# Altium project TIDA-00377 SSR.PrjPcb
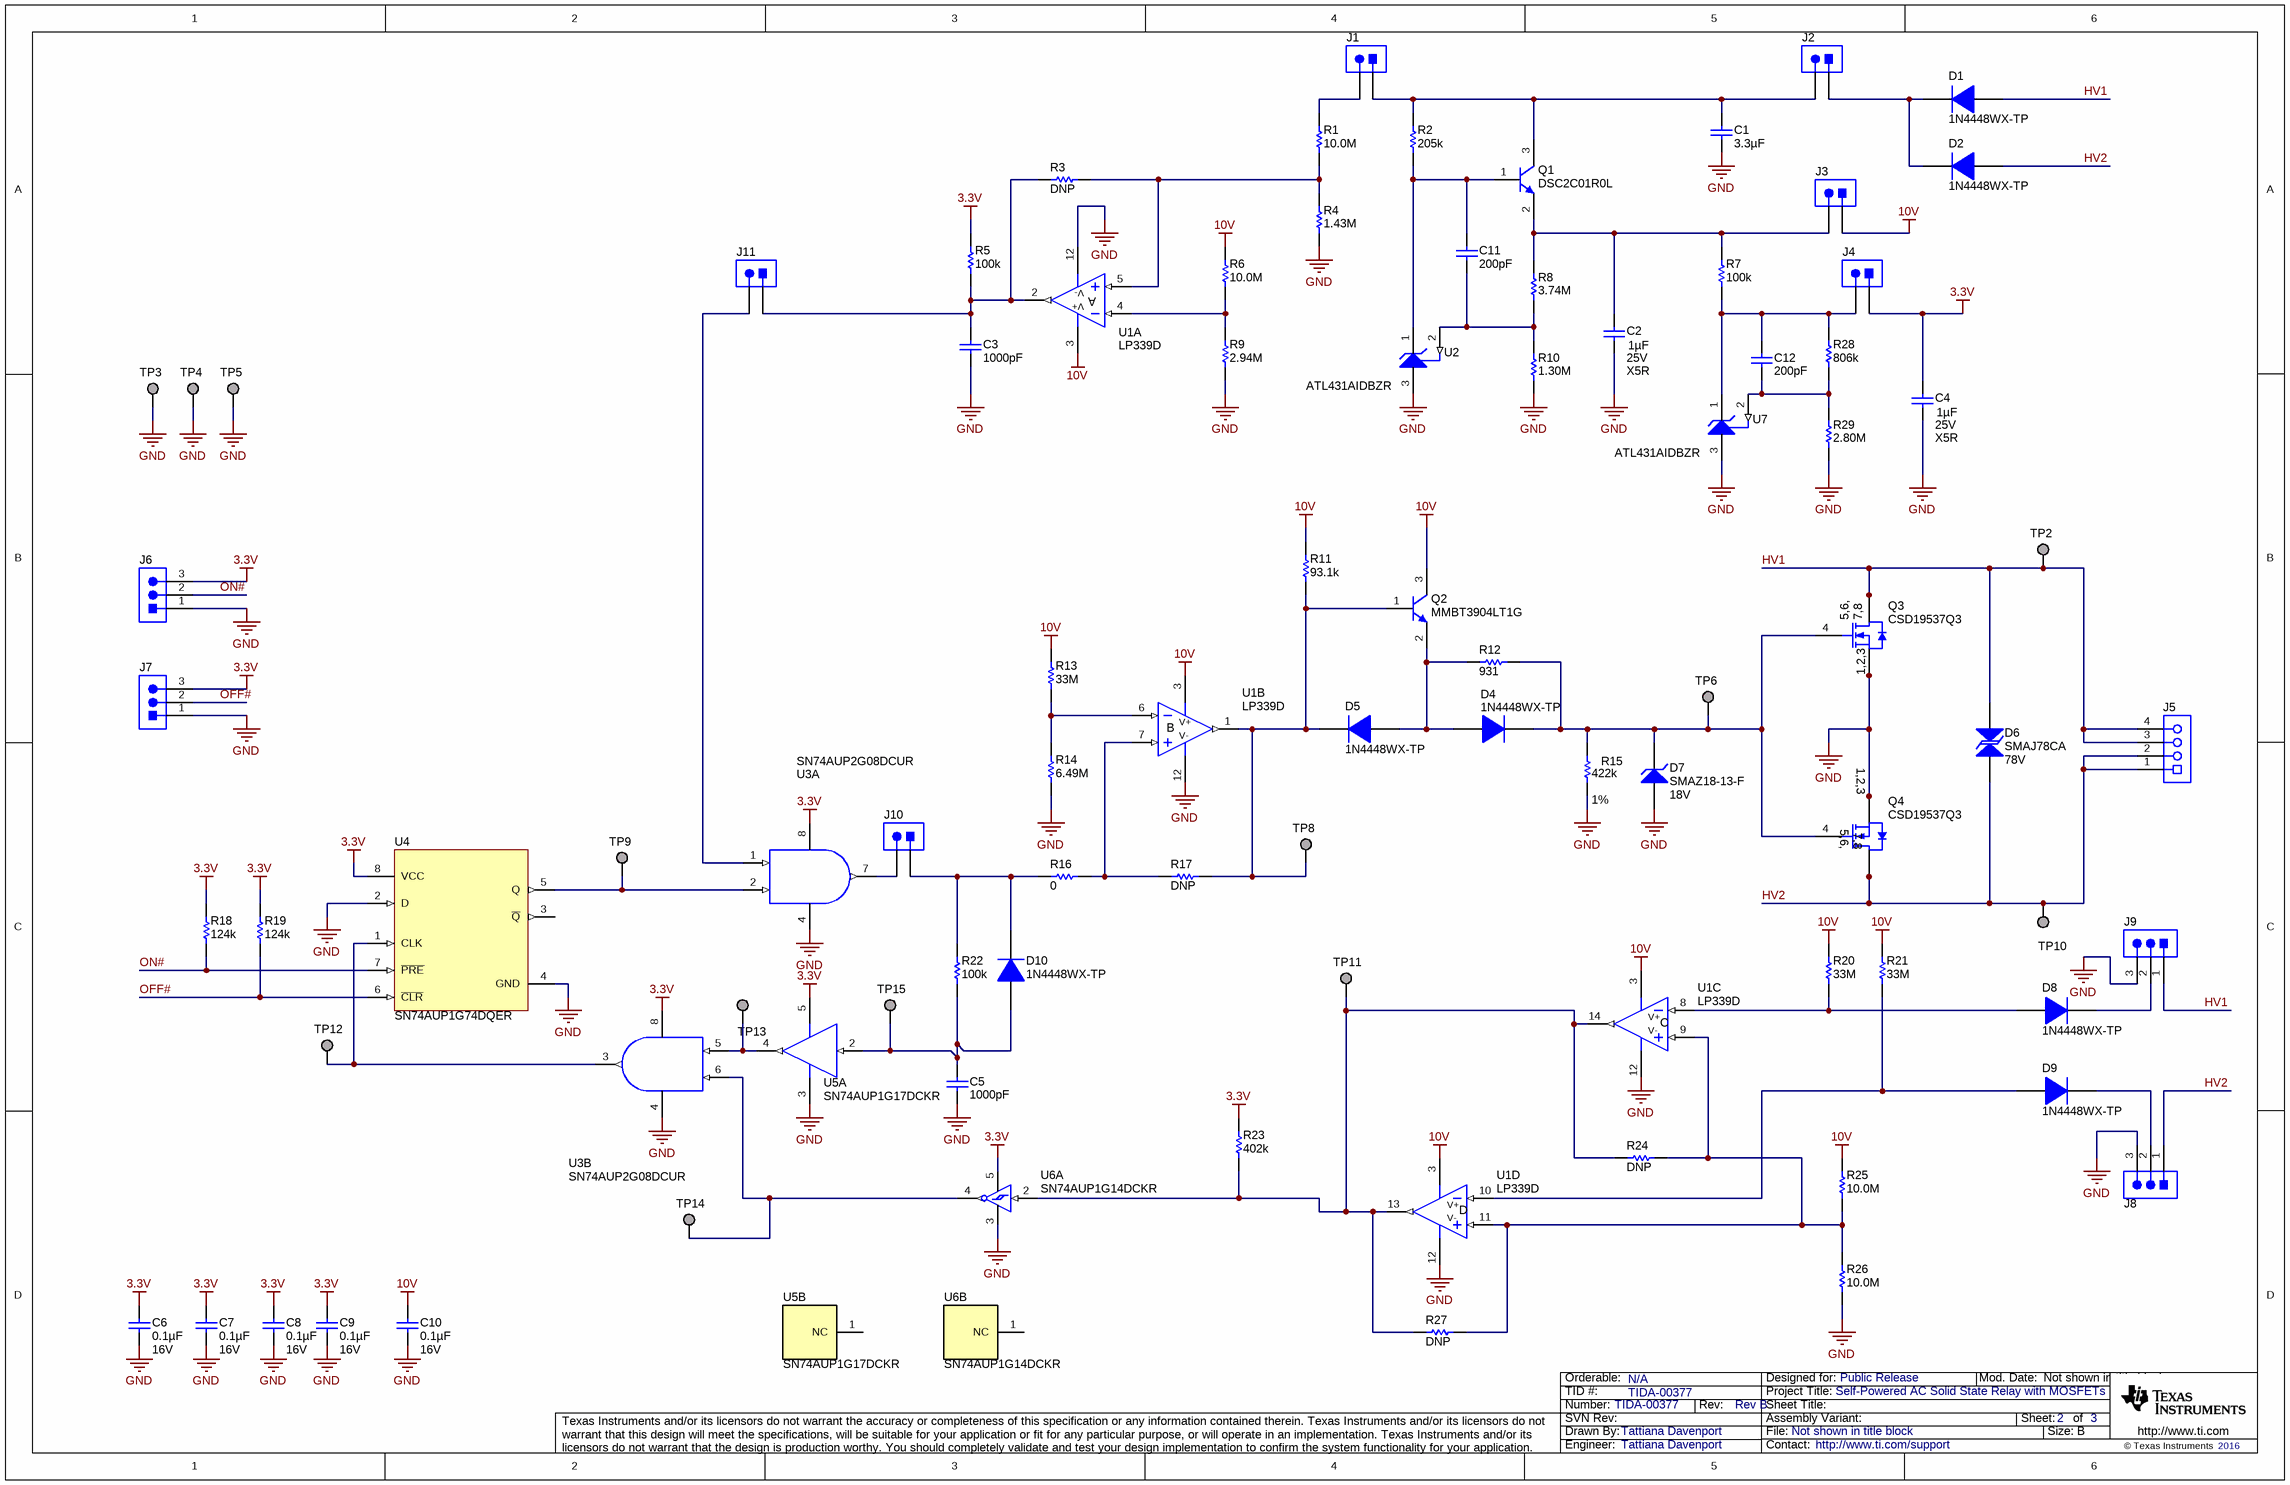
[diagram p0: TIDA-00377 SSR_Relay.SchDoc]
CopyrightYear: 2016; EVM_Orderable: N/A; PCB_Rev: Rev B; PRJ_Customer: Public Release; PRJ_Engineer: Tattiana Davenport; PRJ_Number: TIDA-00377; PRJ_Title: Self-Powered AC Solid State Relay with MOSFETs; SCH_Rev: Rev B; TechSupport: http://www.ti.com/support; TID: TIDA-00377
3 sheets, 114 parts. Net scope: global (net labels, ports and power ports of the same name join across sheets).
Board file: TIDA-00377 SSR_TID.PcbDoc
Sheets:
  TIDA-00377 SSR_Relay.SchDoc
  TIDA-00377 SSR_CoverSheet.SchDoc
  TIDA-00377 SSR_TID_Hardware.SchDoc

## Sheet TIDA-00377 SSR_Relay.SchDoc
size 431 x 279 mm; Date: Not shown in title block; ApprovedBy: Not shown in title block; CheckedBy: Not shown in title block; Author: Not shown in title block; CompanyName: Not shown in title block; DrawnBy: Tattiana Davenport; Engineer: Not shown in title block; Organization: Not shown in title block; Address1: Not shown in title block; Address2: Not shown in title block; Address3: Not shown in title block; Address4: Not shown in title block; DocumentNumber: 1; Revision: Use project parameter SCH_Rev; SheetNumber: 2; SheetTotal: 3; PageSetup: Record=PageOptions¦CenterHorizontal=True¦CenterVertical=True¦PrintScale=1.00¦XCorrection=1.00¦YCorrection=1.00¦PrintKind=0¦BorderSize=5000000¦LeftOffset=0¦BottomOffset=0¦Orientation=2¦PaperLength=1000¦PaperWidth=1000¦Scale=100¦PaperSource=15¦PrintQuality=-3¦MediaType=1¦DitherType=10¦PrintScaleMode=1¦PaperKind=Letter¦PaperIndex=1

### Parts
C1  ValueDisplayed: 3.3µF  [1210]  (hidden comment: C3225X7S2A335M200AB)
C2  ValueDisplayed: 1µF  Value2: 25V  TempCo: X5R  [0603]  (hidden comment: GRM188R61E105KA12D)
C3  ValueDisplayed: 1000pF  [0603]  (hidden comment: GRM188R71E102KA01D)
C4  ValueDisplayed: 1µF  Value2: 25V  TempCo: X5R  [0603]  (hidden comment: GRM188R61E105KA12D)
C5  ValueDisplayed: 1000pF  [0603]  (hidden comment: GRM188R71E102KA01D)
C6  ValueDisplayed: 0.1µF  Value2: 16V  [0603]  (hidden comment: GRM188R71C104KA01D)
C7  ValueDisplayed: 0.1µF  Value2: 16V  [0603]  (hidden comment: GRM188R71C104KA01D)
C8  ValueDisplayed: 0.1µF  Value2: 16V  [0603]  (hidden comment: GRM188R71C104KA01D)
C9  ValueDisplayed: 0.1µF  Value2: 16V  [0603]  (hidden comment: GRM188R71C104KA01D)
C10  ValueDisplayed: 0.1µF  Value2: 16V  [0603]  (hidden comment: GRM188R71C104KA01D)
C11  ValueDisplayed: 200pF  [0603]  (hidden comment: GRM1885C1H201JA01D)
C12  ValueDisplayed: 200pF  [0603]  (hidden comment: GRM1885C1H201JA01D)
D1  1N4448WX-TP  [sod-323]
D2  1N4448WX-TP  [sod-323]
D4  1N4448WX-TP  [sod-323]
D5  1N4448WX-TP  [sod-323]
D6  SMAJ78CA  value 78V  [SMA]
D7  SMAZ18-13-F  value 18V  [SMA]
D8  1N4448WX-TP  [sod-323]
D9  1N4448WX-TP  [sod-323]
D10  1N4448WX-TP  [sod-323]
J1  5-146278-2  [TE_5-146278-2]  (value not drawn)
J2  5-146278-2  [TE_5-146278-2]  (value not drawn)
J3  5-146278-2  [TE_5-146278-2]  (value not drawn)
J4  5-146278-2  [TE_5-146278-2]  (value not drawn)
J5  282834-4  [TEC_282834-4]  (value not drawn)
J6  5-146278-3  [TE_5-146278-3]  (value not drawn)
J7  5-146278-3  [TE_5-146278-3]  (value not drawn)
J8  5-146278-3  [TE_5-146278-3]  (value not drawn)
J9  5-146278-3  [TE_5-146278-3]  (value not drawn)
J10  5-146278-2  [TE_5-146278-2]  (value not drawn)
J11  5-146278-2  [TE_5-146278-2]  (value not drawn)
Q1  DSC2C01R0L  [SOT-23]
Q2  MMBT3904LT1G  [SOT-23]
Q3  CSD19537Q3  [DQG0008A]
Q4  CSD19537Q3  [DQG0008A]
R1  ValueDisplayed: 10.0M  [0805_HV]  (hidden comment: CRCW080510M0FKEA)
R2  ValueDisplayed: 205k  [0805_HV]  (hidden comment: CRCW0805205KFKEA)
R3  ValueDisplayed: DNP  [0805_HV]  (hidden comment: CRCW08050000Z0EA)
R4  ValueDisplayed: 1.43M  [0805_HV]  (hidden comment: CRCW08051M43FKEA)
R5  ValueDisplayed: 100k  [0805_HV]  (hidden comment: CRCW0805100KFKEA)
R6  ValueDisplayed: 10.0M  [0805_HV]  (hidden comment: CRCW080510M0FKEA)
R7  ValueDisplayed: 100k  [0805_HV]  (hidden comment: CRCW0805100KFKEA)
R8  ValueDisplayed: 3.74M  [0805_HV]  (hidden comment: CRCW08053M74FKEA)
R9  ValueDisplayed: 2.94M  [0805_HV]  (hidden comment: CRCW08052M94FKEA)
R10  ValueDisplayed: 1.30M  [0805_HV]  (hidden comment: CRCW08051M30FKEA)
R11  ValueDisplayed: 93.1k  [0805_HV]  (hidden comment: CRCW080593K1FKEA)
R12  ValueDisplayed: 931  [0805_HV]  (hidden comment: CRCW0805931RFKEA)
R13  ValueDisplayed: 33M  [0805_HV]  (hidden comment: RC0805JR-0733ML)
R14  ValueDisplayed: 6.49M  [0805_HV]  (hidden comment: CRCW08056M49FKEA)
R15  ValueDisplayed: 422k  Value1: 1%  [0805_HV]  (hidden comment: CRCW0805422KFKEA)
R16  ValueDisplayed: 0  [0805_HV]  (hidden comment: CRCW08050000Z0EA)
R17  ValueDisplayed: DNP  [0805_HV]  (hidden comment: CRCW08050000Z0EA)
R18  ValueDisplayed: 124k  [0402]  (hidden comment: CRCW0402124KFKED)
R19  ValueDisplayed: 124k  [0402]  (hidden comment: CRCW0402124KFKED)
R20  ValueDisplayed: 33M  [0805_HV]  (hidden comment: RC0805JR-0733ML)
R21  ValueDisplayed: 33M  [0805_HV]  (hidden comment: RC0805JR-0733ML)
R22  ValueDisplayed: 100k  [0805_HV]  (hidden comment: CRCW0805100KFKEA)
R23  ValueDisplayed: 402k  [0805_HV]  (hidden comment: CRCW0805402KFKEA)
R24  ValueDisplayed: DNP  [0805_HV]  (hidden comment: CRCW08050000Z0EA)
R25  ValueDisplayed: 10.0M  [0805_HV]  (hidden comment: CRCW080510M0FKEA)
R26  ValueDisplayed: 10.0M  [0805_HV]  (hidden comment: CRCW080510M0FKEA)
R27  ValueDisplayed: DNP  [0805_HV]  (hidden comment: CRCW08050000Z0EA)
R28  ValueDisplayed: 806k  [0805_HV]  (hidden comment: CRCW0805806KFKEA)
R29  ValueDisplayed: 2.80M  [0805_HV]  (hidden comment: CRCW08052M80FKEA)
TP2  TESTPOINT  [Keystone_5019]  (value not drawn)  (no BOM)
TP3  TESTPOINT  [Keystone_5019]  (value not drawn)  (no BOM)
TP4  TESTPOINT  [Keystone_5019]  (value not drawn)  (no BOM)
TP5  TESTPOINT  [Keystone_5019]  (value not drawn)  (no BOM)
TP6  TESTPOINT  [Keystone_5019]  (value not drawn)  (no BOM)
TP8  TESTPOINT  [Keystone_5019]  (value not drawn)  (no BOM)
TP9  TESTPOINT  [Keystone_5019]  (value not drawn)  (no BOM)
TP10  TESTPOINT  [Keystone_5019]  (value not drawn)  (no BOM)
TP11  TESTPOINT  [Keystone_5019]  (value not drawn)  (no BOM)
TP12  TESTPOINT  [Keystone_5019]  (value not drawn)  (no BOM)
TP13  TESTPOINT  [Keystone_5019]  (value not drawn)  (no BOM)
TP14  TESTPOINT  [Keystone_5019]  (value not drawn)  (no BOM)
TP15  TESTPOINT  [Keystone_5019]  (value not drawn)  (no BOM)
U1  LP339D  [D0014A_N]  (parts A,B,C,D of 4)
U2  ATL431AIDBZR  [DBZ0003A_M]
U3  SN74AUP2G08DCUR  [DCU0008A_N]  (parts A,B of 2)
U4  SN74AUP1G74DQER  [DQE0008A]
U5  SN74AUP1G17DCKR  [DCK0005A_N]  (parts A,B of 2)
U6  SN74AUP1G14DCKR  [DCK0005A_N]  (parts A,B of 2)
U7  ATL431AIDBZR  [DBZ0003A_M]

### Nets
3.3V: C4.2 C6.2 C7.2 C8.2 C9.2 J4.1 J6.3 J7.3 R5.1 R18.2 R19.2 R23.1 U3.8(V+) U4.8(VCC) U5.5(VCC) U6.5(VCC)
10V: C10.2 J3.1 Q2.3(C) R6.1 R11.1 R13.1 R20.1 R21.1 R25.1 U1.3(V+)
GND: C1.1 C2.1 C3.1 C4.1 C5.1 C6.1 C7.1 C8.1 C9.1 C10.1 D7.2(A) J6.1 J7.1 J8.3 J9.3 Q3.1(S) Q3.2(S) Q3.3(S) Q4.1(S) Q4.2(S) Q4.3(S) R4.2 R9.2 R10.2 R14.2 R15.1 R26.2 R29.2 TP3.1 TP4.1 TP5.1 U1.12(V-) U2.3(ANODE) U3.4(V-) U4.2(D) U4.4(GND) U5.3(GND) U6.3(GND) U7.3(ANODE)
HV1: D1.2(A) D6.2 J5.3 J5.4 J9.1 Q3.5(D) Q3.6(D) Q3.7(D) Q3.8(D) Q3.9(D) TP2.1
HV2: D2.2(A) D6.1 J5.1 J5.2 J8.1 Q4.5(D) Q4.6(D) Q4.7(D) Q4.8(D) Q4.9(D) TP10.1
OFF#: J7.2 R19.1 U4.6(~{CLR})
ON#: J6.2 R18.1 U4.7(~{PRE})
NetC1_2: C1.2 J1.1 J2.2 Q1.3(C) R2.1
NetC2_2: C2.2 J3.2 Q1.2(E) R7.1 R8.1
NetC3_2: C3.2 J11.1 R3.1 R5.2 U1.2(OUT1)
NetC5_2: C5.2 D10.2(A) R22.2 TP15.1 U5.2(A)
NetC11_1: C11.1 R8.2 R10.1 U2.2(REF)
NetC11_2: C11.2 Q1.1(B) R2.2 U2.1(CATHODE)
NetC12_1: C12.1 R28.2 R29.1 U7.2(REF)
NetC12_2: C12.2 J4.2 R7.2 R28.1 U7.1(CATHODE)
NetD1_1: D1.1(K) D2.1(K) J2.1
NetD4_1: D4.1(K) D7.1(K) Q3.4(G) Q4.4(G) R12.2 R15.2 TP6.1
NetD4_2: D4.2(A) D5.2(A) Q2.2(E) R12.1
NetD5_1: D5.1(K) Q2.1(B) R11.2 R17.2 TP8.1 U1.1(OUT2)
NetD8_1: D8.1(K) J9.2
NetD8_2: D8.2(A) R20.2 U1.8(-IN3)
NetD9_1: D9.1(K) J8.2
NetD9_2: D9.2(A) R21.2 U1.10(-IN4)
NetD10_1: D10.1(K) J10.1 R16.1 R22.1
NetJ1_2: J1.2 R1.1
NetJ10_2: J10.2 U3.7(1Y)
NetJ11_2: J11.2 U3.1(1A)
NetR1_2: R1.2 R3.2 R4.1 U1.5(+IN1)
NetR6_2: R6.2 R9.1 U1.4(-IN1)
NetR13_2: R13.2 R14.1 U1.6(-IN2)
NetR16_2: R16.2 R17.1 U1.7(+IN2)
NetR23_2: R23.2 R24.1 R27.1 TP11.1 U1.13(OUT4) U1.14(OUT3) U6.2(A)
NetR24_2: R24.2 R25.2 R26.1 R27.2 U1.9(+IN3) U1.11(+IN4)
NetTP9_1: TP9.1 U3.2(1B) U4.5(Q)
NetTP12_1: TP12.1 U3.3(2Y) U4.1(CLK)
NetTP13_1: TP13.1 U3.5(2A) U5.4(Y)
NetTP14_1: TP14.1 U3.6(2B) U6.4(Y)

Not connected (* = marked no-connect by the designer): U4 3(~{Q}); U5 1(NC); U6 1(NC)

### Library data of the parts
C1 = C3225X7S2A335M200AB: CAP, CERM, 3.3 µF, 100 V, +/- 20%, X7S, 1210; Manufacturer: TDK; Polarized: N; CompType: Capacitor; Value: 3.3uF; U/M: EA; Cap_F: 0.0000033; Tolerance_%: 20; Value1: Unknown; VDC_V: 100; Value2: 100V; TaMin_C: -55; TaMax_C: 125; AEC Category: Q200
C2 C4 = GRM188R61E105KA12D: CAP, CERM, 1 µF, 25 V, +/- 10%, X5R, 0603; Manufacturer: MuRata; Polarized: N; CompType: Capacitor; Value: 1uF; U/M: EA; Cap_F: 0.000001; Tolerance_%: 10; Value1: Unknown; VDC_V: 25; TaMin_C: -55; TaMax_C: 85; AEC Category: Q200
C3 C5 = GRM188R71E102KA01D: CAP, CERM, 1000 pF, 25 V, +/- 10%, X7R, 0603; Manufacturer: MuRata; Polarized: N; CompType: Capacitor; Value: 1000pF; U/M: EA; Cap_F: 0.000000001; Tolerance_%: 10; Value1: Unknown; VDC_V: 25; Value2: 25V; TaMin_C: -55; TaMax_C: 125; AEC Category: Q200
C6-C10 = GRM188R71C104KA01D: CAP, CERM, 0.1 µF, 16 V, +/- 10%, X7R, 0603; Manufacturer: MuRata; Polarized: N; CompType: Capacitor; Value: 0.1uF; U/M: EA; Cap_F: 0.0000001; Tolerance_%: 10; Value1: Unknown; VDC_V: 16; TaMin_C: -55; TaMax_C: 125; AEC Category: Q200
C11 C12 = GRM1885C1H201JA01D: CAP, CERM, 200 pF, 50 V, +/- 5%, C0G/NP0, 0603; Manufacturer: MuRata; Polarized: N; CompType: Capacitor; Value: 200pF; U/M: EA; Cap_F: 0.0000000002; Tolerance_%: 5; Value1: Unknown; VDC_V: 50; Value2: 50V; TaMin_C: -55; TaMax_C: 125; AEC Category: Q200
D1 D2 D4 D5 D8-D10 = 1N4448WX-TP: Diode, Switching, 75 V, 0.25 A, SOD-323; Manufacturer: Micro Commercial Components; U/M: EA; Value: 75V; Value1: 0.25A; Io_A: 0.25; Vr_V: 75; TJmax_C: 150; AEC Category: Q101
D6 = SMAJ78CA: Diode, TVS, Bi, 78 V, 400 W, SMA; Manufacturer: Littelfuse; U/M: EA; Power_W: 400; Vr_V: 78; Value1: 400W; RJA_CperW: 120; AEC Category: Q101
D7 = SMAZ18-13-F: Diode, Zener, 18 V, 1 W, AEC-Q101, SMA; Manufacturer: Diodes Inc.; SymbolCreator: a0412235; U/M: EA; Power_W: 1; Vz_V: 18; Value1: 1W; RJA_CperW: 125; AEC Category: Q101; AEC Qualified: Y
J1-J4 J10 J11 = 5-146278-2: Header, 100mil, 2x1, Tin, TH; Manufacturer: TE Connectivity; SymbolCreator: a0412235; U/M: EA
J5 = 282834-4: Terminal Block, 100mil, 4X1 TH; Manufacturer: TE Connectivity; SymbolCreator: a0411947
J6-J9 = 5-146278-3: Header, 100mil, 3x1, Tin, TH; Manufacturer: TE Connectivity; SymbolCreator: a0799628
Q1 = DSC2C01R0L, Panasonic: Transistor, NPN, 100 V, 0.02 A, SOT-23; CompType: BJT; PNP: 0; NPN: 1; Vceo_V: 100; Vcesat1_V: 0.05; Value: 100 V; IcRated_A: 0.02; Value1: 0.02 A; HfeMax: 1200; TaMin_C: -40; TaMax_C: 85; U/M: EA; AEC Category: Q101; AEC Qualified: N
Q2 = MMBT3904LT1G, ON Semiconductor: Transistor, NPN, 40 V, 0.2 A, SOT-23; CompType: BJT; PNP: 0; NPN: 1; Vceo_V: 40; Vcesat1_V: 0.3; Value: 40 V; IcRated_A: 0.2; Value1: 0.2 A; HfeMax: 300; TaMin_C: -55; TaMax_C: 150; U/M: EA; AEC Category: Q101
Q3 Q4 = CSD19537Q3: MOSFET, N-CH, 100 V, 50 A, DQG0008A; Manufacturer: Texas Instruments; Alternate Manufacturer: None; U/M: EA; ChType: N; Value: 100V; VdsMax_V: 100; Value1: ? ohm; Value2: 16 nC; QgTyp_nC: 16; Vgs_V: 20; IdsMax_A: 50; AEC Category: Q101
R1 R6 R25 R26 = CRCW080510M0FKEA: RES, 10.0 M, 1%, 0.125 W, 0805; Manufacturer: Vishay-Dale; CompType: Resistor; Value: 10.0Meg; Res_ohm: 10000000; Value_Code: 10M0; Tolerance_%: 1; Power_W: 0.125; Value2: 0.125W; VDC_V: 150; TempCo: 100 ppm/C; EIA_Code: E96; U/M: EA; AEC Category: Q200
R2 = CRCW0805205KFKEA: RES, 205 k, 1%, 0.125 W, 0805; Manufacturer: Vishay-Dale; CompType: Resistor; Value: 205k; Res_ohm: 205000; Tolerance_%: 1; Power_W: 0.125; Value2: 0.125W; VDC_V: 150; TempCo: 100 ppm/C; EIA_Code: E96; U/M: EA; AEC Category: Q200
R3 R17 R24 R27 = CRCW08050000Z0EA: RES, 0, 5%, 0.125 W, 0805; Manufacturer: Vishay-Dale; CompType: Resistor; Res_ohm: 0; Value_Code: 0000; Tolerance_%: 5; Power_W: 0.125; Value2: 0.125W; VDC_V: 150; TempCo: 200 ppm/C; EIA_Code: E24; U/M: EA; AEC Category: Q200
R4 = CRCW08051M43FKEA: RES, 1.43 M, 1%, 0.125 W, 0805; Manufacturer: Vishay-Dale; CompType: Resistor; Value: 1.43Meg; Res_ohm: 1430000; Value_Code: 1M43; Tolerance_%: 1; Power_W: 0.125; Value2: 0.125W; VDC_V: 150; TempCo: 100 ppm/C; EIA_Code: E96; U/M: EA; AEC Category: Q200
R5 R7 R22 = CRCW0805100KFKEA: RES, 100 k, 1%, 0.125 W, 0805; Manufacturer: Vishay-Dale; CompType: Resistor; Value: 100k; Res_ohm: 100000; Tolerance_%: 1; Power_W: 0.125; Value2: 0.125W; VDC_V: 150; TempCo: 100 ppm/C; EIA_Code: E96; U/M: EA; AEC Category: Q200
R8 = CRCW08053M74FKEA: RES, 3.74 M, 1%, 0.125 W, 0805; Manufacturer: Vishay-Dale; CompType: Resistor; Value: 3.74Meg; Res_ohm: 3740000; Value_Code: 3M74; Tolerance_%: 1; Power_W: 0.125; Value2: 0.125W; VDC_V: 150; TempCo: 100 ppm/C; EIA_Code: E96; U/M: EA; AEC Category: Q200
R9 = CRCW08052M94FKEA: RES, 2.94 M, 1%, 0.125 W, 0805; Manufacturer: Vishay-Dale; CompType: Resistor; Value: 2.94Meg; Res_ohm: 2940000; Value_Code: 2M94; Tolerance_%: 1; Power_W: 0.125; Value2: 0.125W; VDC_V: 150; TempCo: 100 ppm/C; EIA_Code: E96; U/M: EA; AEC Category: Q200
R10 = CRCW08051M30FKEA: RES, 1.30 M, 1%, 0.125 W, 0805; Manufacturer: Vishay-Dale; CompType: Resistor; Value: 1.30Meg; Res_ohm: 1300000; Value_Code: 1M30; Tolerance_%: 1; Power_W: 0.125; Value2: 0.125W; VDC_V: 150; TempCo: 100 ppm/C; EIA_Code: E96; U/M: EA; AEC Category: Q200
R11 = CRCW080593K1FKEA: RES, 93.1 k, 1%, 0.125 W, 0805; Manufacturer: Vishay-Dale; CompType: Resistor; Value: 93.1k; Res_ohm: 93100; Value_Code: 93k1; Tolerance_%: 1; Power_W: 0.125; Value2: 0.125W; VDC_V: 150; TempCo: 100 ppm/C; EIA_Code: E96; U/M: EA; AEC Category: Q200
R12 = CRCW0805931RFKEA: RES, 931, 1%, 0.125 W, 0805; Manufacturer: Vishay-Dale; CompType: Resistor; Value: 931; Value_Code: 931R; Tolerance_%: 1; Power_W: 0.125; Value2: 0.125W; VDC_V: 150; TempCo: 100 ppm/C; EIA_Code: E96; U/M: EA; AEC Category: Q200
R13 R20 R21 = RC0805JR-0733ML: RES, 33 M, 5%, 0.125 W, 0805; Manufacturer: Yageo America; CompType: Resistor; Value: 33Meg; Res_ohm: 33000000; Value_Code: 33M0; Tolerance_%: 5; Power_W: 0.125; Value2: 0.125W; VDC_V: 150; TempCo: 300 ppm/C; U/M: EA; AEC Category: Q200; AEC Qualified: N
R14 = CRCW08056M49FKEA: RES, 6.49 M, 1%, 0.125 W, 0805; Manufacturer: Vishay-Dale; CompType: Resistor; Value: 6.49Meg; Res_ohm: 6490000; Value_Code: 6M49; Tolerance_%: 1; Power_W: 0.125; Value2: 0.125W; VDC_V: 150; TempCo: 100 ppm/C; EIA_Code: E96; U/M: EA; AEC Category: Q200
R15 = CRCW0805422KFKEA: RES, 422 k, 1%, 0.125 W, 0805; Manufacturer: Vishay-Dale; CompType: Resistor; Value: 422k; Res_ohm: 422000; Tolerance_%: 1; Power_W: 0.125; Value2: 0.125W; VDC_V: 150; TempCo: 100 ppm/C; EIA_Code: E96; U/M: EA; AEC Category: Q200
R16 = CRCW08050000Z0EA: RES, 0, 5%, 0.125 W, 0805; Manufacturer: Vishay-Dale; CompType: Resistor; Value: 0; Value_Code: 0000; Tolerance_%: 5; Power_W: 0.125; Value2: 0.125W; VDC_V: 150; TempCo: 200 ppm/C; EIA_Code: E24; U/M: EA; AEC Category: Q200
R18 R19 = CRCW0402124KFKED: RES, 124 k, 1%, 0.063 W, 0402; Manufacturer: Vishay-Dale; CompType: Resistor; Value: 124k; Res_ohm: 124000; Tolerance_%: 1; Power_W: 0.063; Value2: 0.063W; VDC_V: 50; TempCo: 100 ppm/C; EIA_Code: E96; U/M: EA; AEC Category: Q200
R23 = CRCW0805402KFKEA: RES, 402 k, 1%, 0.125 W, 0805; Manufacturer: Vishay-Dale; CompType: Resistor; Value: 402k; Res_ohm: 402000; Tolerance_%: 1; Power_W: 0.125; Value2: 0.125W; VDC_V: 150; TempCo: 100 ppm/C; EIA_Code: E96; U/M: EA; AEC Category: Q200
R28 = CRCW0805806KFKEA: RES, 806 k, 1%, 0.125 W, 0805; Manufacturer: Vishay-Dale; CompType: Resistor; Value: 806k; Res_ohm: 806000; Tolerance_%: 1; Power_W: 0.125; Value2: 0.125W; VDC_V: 150; TempCo: 100 ppm/C; EIA_Code: E96; U/M: EA; AEC Category: Q200
R29 = CRCW08052M80FKEA: RES, 2.80 M, 1%, 0.125 W, 0805; Manufacturer: Vishay-Dale; CompType: Resistor; Value: 2.80Meg; Res_ohm: 2800000; Value_Code: 2M80; Tolerance_%: 1; Power_W: 0.125; Value2: 0.125W; VDC_V: 150; TempCo: 100 ppm/C; EIA_Code: E96; U/M: EA; AEC Category: Q200
TP2-TP6 TP8-TP15 = 5019: Test Point, Miniature, SMT; Manufacturer: Keystone; CompType: Test Point Loop
U1 = LP339D: Quad, Low-Power, General Purpose Differential Comparator, D0014A; Manufacturer: Texas Instruments; SymbolCreator: Altium; CompType: OpAmp IC
U2 U7 = ATL431AIDBZR: 2.5V Low Iq Adjustable Precision Shunt Regulator, DBZ0003A; Manufacturer: Texas Instruments; SymbolCreator: a0412235; CompType: IC; U/M: EA
U3 = SN74AUP2G08DCUR: LOW-POWER DUAL 2-INPUT POSITIVE-AND GATE, DCU0008A; Manufacturer: Texas Instruments; SymbolCreator: Altium; CompType: IC; U/M: EA
U4 = SN74AUP1G74DQER: LOW-POWER SINGLE POSITIVE-EDGE-TRIGGERED D-TYPE FLIP-FLOP WITH CLEAR AND PRESET, DQE0008A; Manufacturer: Texas Instruments; SymbolCreator: a0799628; CompType: IC; U/M: EA
U5 = SN74AUP1G17DCKR: LOW-POWER SINGLE SCHMITT-TRIGGER BUFFER, DCK0005A; Alternate PartNumber: SN74AUP1G17DCKT; Manufacturer: Texas Instruments; SymbolCreator: a0411947; CompType: IC; U/M: EA; SizeX_mm: 2.1; SizeY_mm: 2; SizeZ_mm: 1.1
U6 = SN74AUP1G14DCKR: LOW-POWER SINGLE SCHMITT-TRIGGER INVERTER, DCK0005A; Alternate PartNumber: SN74AUP1G14DCKT; Manufacturer: Texas Instruments; SymbolCreator: a0411947; CompType: IC; U/M: EA; SizeX_mm: 2.1; SizeY_mm: 2; SizeZ_mm: 1.1

## Sheet TIDA-00377 SSR_CoverSheet.SchDoc: CoverSheet
size 431 x 279 mm; Date: Not shown in title block; ApprovedBy: Not shown in title block; CheckedBy: Not shown in title block; Author: Not shown in title block; CompanyName: Not shown in title block; DrawnBy: Jarrod Krebs; Engineer: Not shown in title block; Organization: Not shown in title block; Address1: Not shown in title block; Address2: Not shown in title block; Address3: Not shown in title block; Address4: Not shown in title block; DocumentNumber: 1; Revision: Use project parameter SCH_Rev; SheetNumber: 1; SheetTotal: 3; PageSetup: Record=PageOptions¦CenterHorizontal=True¦CenterVertical=True¦PrintScale=1.00¦XCorrection=1.00¦YCorrection=1.00¦PrintKind=0¦BorderSize=5000000¦LeftOffset=0¦BottomOffset=0¦Orientation=2¦PaperLength=1000¦PaperWidth=1000¦Scale=100¦PaperSource=15¦PrintQuality=600¦MediaType=1¦DitherType=10¦PaperKind=Letter¦PrintScaleMode=1
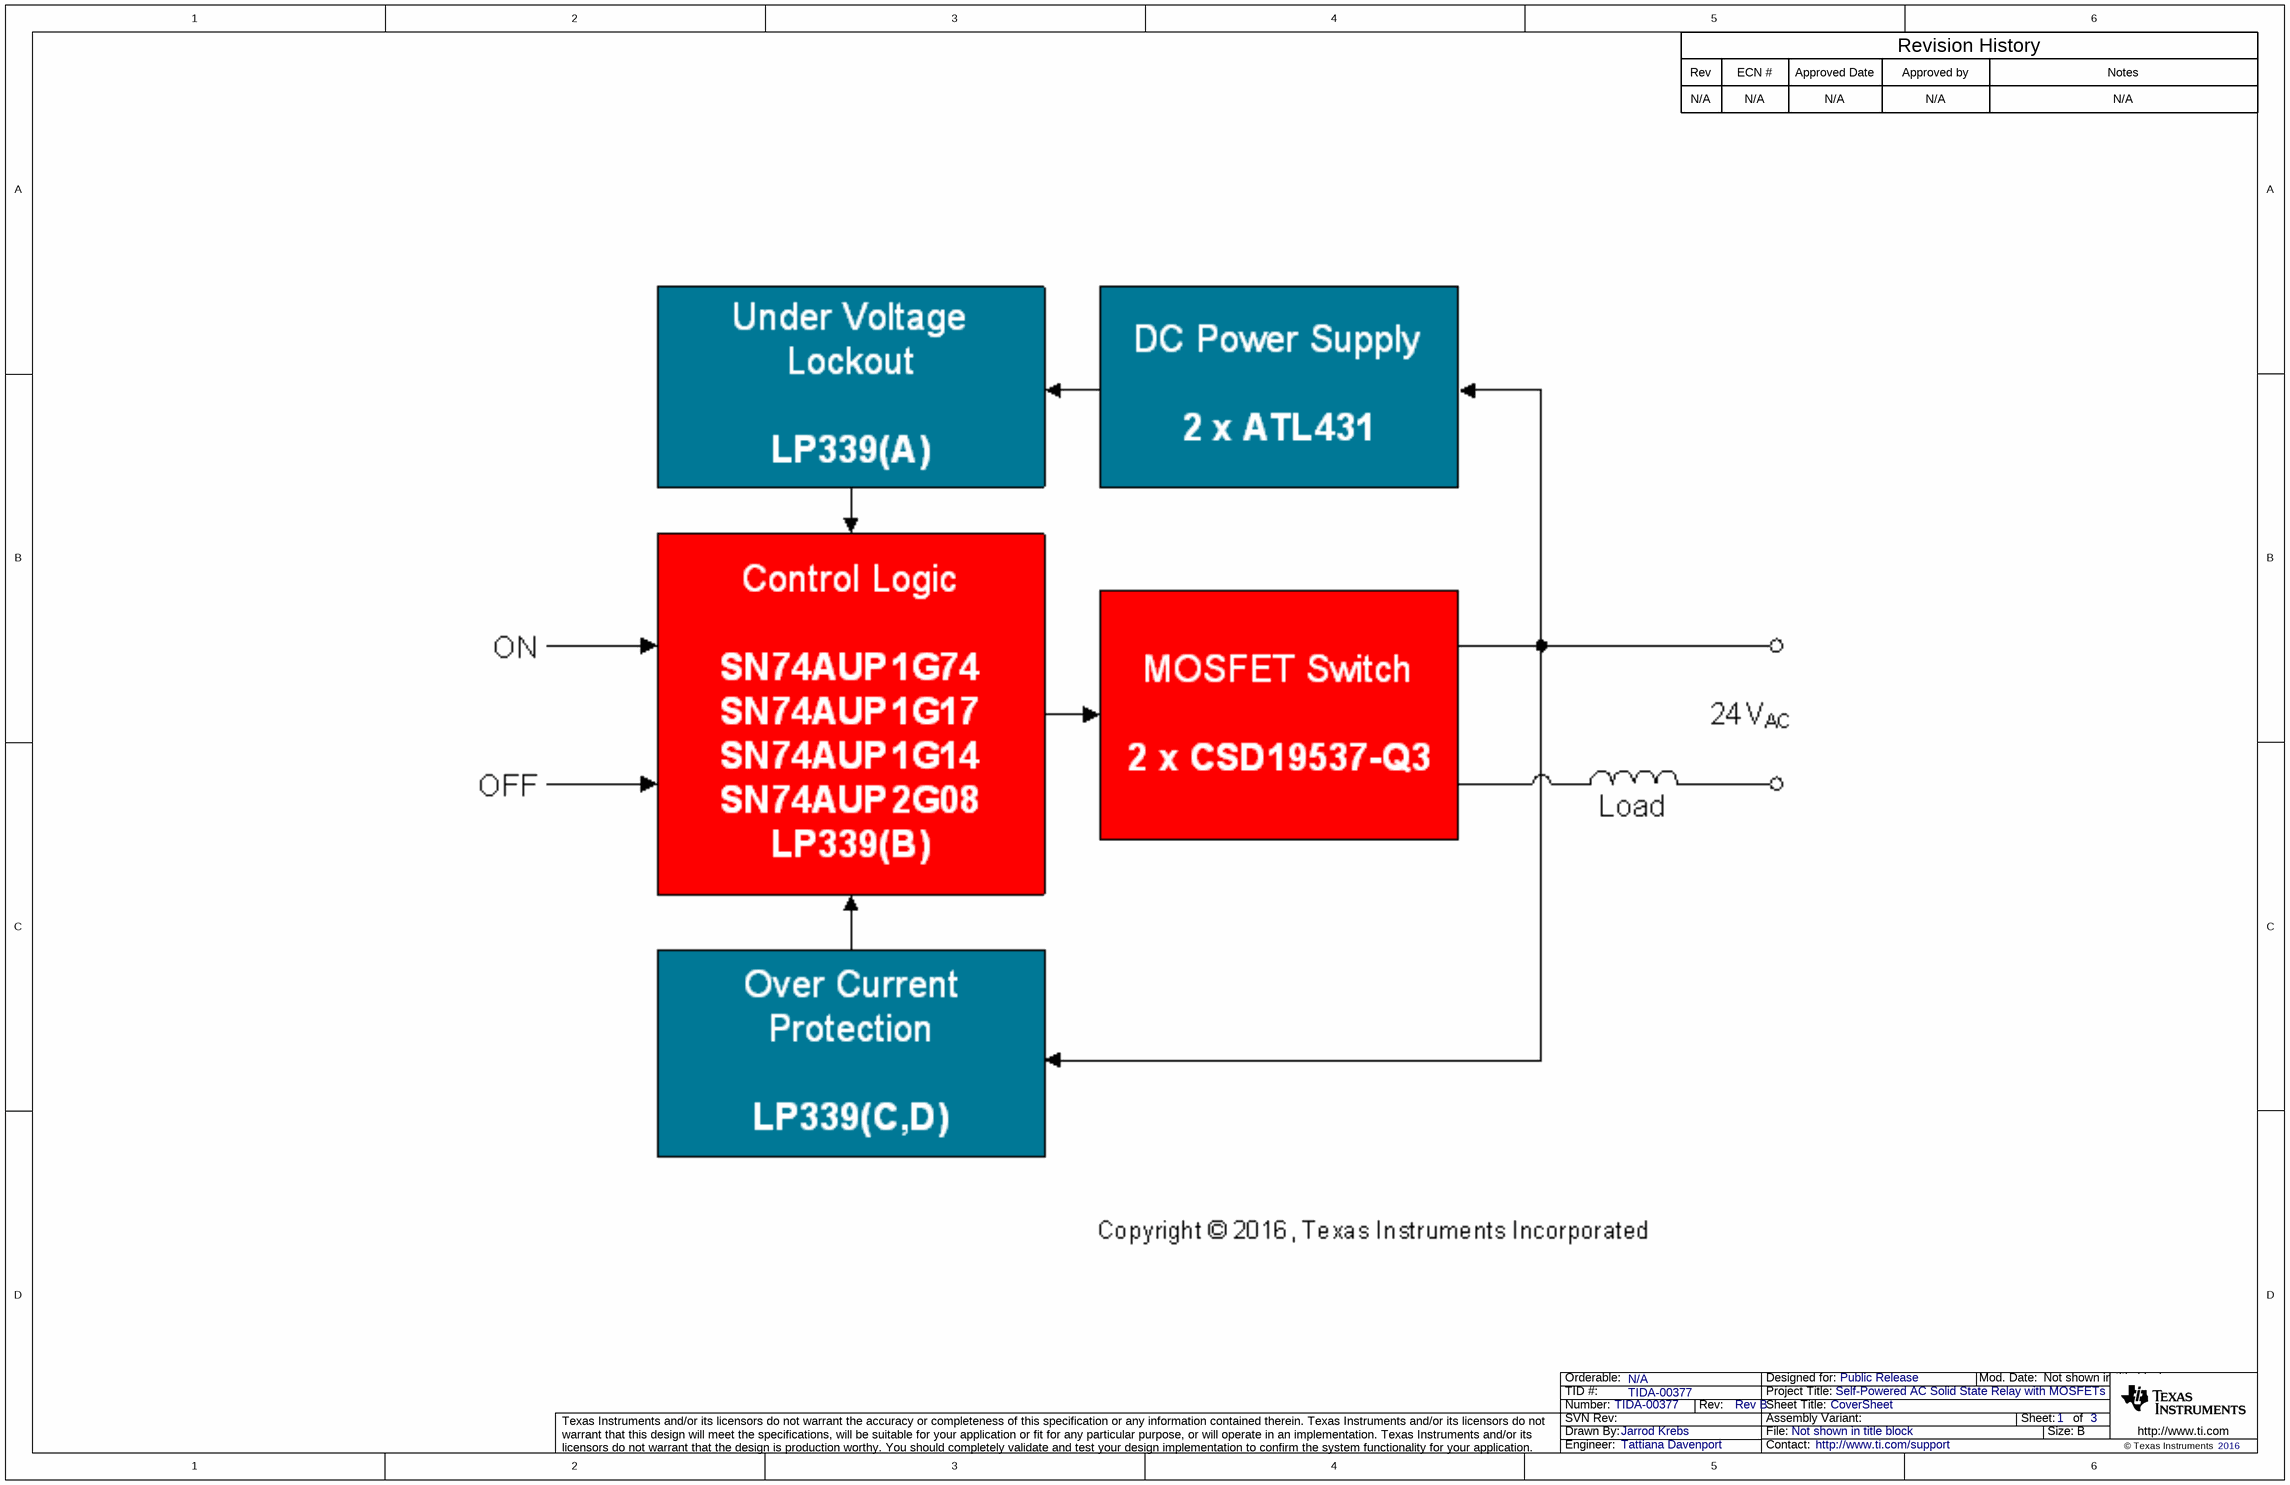
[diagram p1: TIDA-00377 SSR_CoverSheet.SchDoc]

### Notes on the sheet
- Rev
- N/A
- ECN #
- Approved Date
- Approved by
- Revision History
- Notes

## Sheet TIDA-00377 SSR_TID_Hardware.SchDoc: Hardware
size 431 x 279 mm; VersionControl_RevNumber: Use project parameter SCH_Rev; Date: Not shown in title block; ApprovedBy: Not shown in title block; CheckedBy: Not shown in title block; Author: Not shown in title block; CompanyName: Not shown in title block; DrawnBy: Tattiana Davenport; Engineer: Not shown in title block; Organization: Not shown in title block; Address1: Not shown in title block; Address2: Not shown in title block; Address3: Not shown in title block; Address4: Not shown in title block; DocumentNumber: 1; Revision: Use project parameter SCH_Rev; SheetNumber: 3; SheetTotal: 3; PageSetup: Record=PageOptions¦CenterHorizontal=True¦CenterVertical=True¦PrintScale=1.00¦XCorrection=1.00¦YCorrection=1.00¦PrintKind=0¦BorderSize=5000000¦LeftOffset=0¦BottomOffset=0¦Orientation=2¦PaperLength=1000¦PaperWidth=1000¦Scale=100¦PaperSource=15¦PrintQuality=600¦MediaType=1¦DitherType=10¦PaperKind=Letter¦PrintScaleMode=1
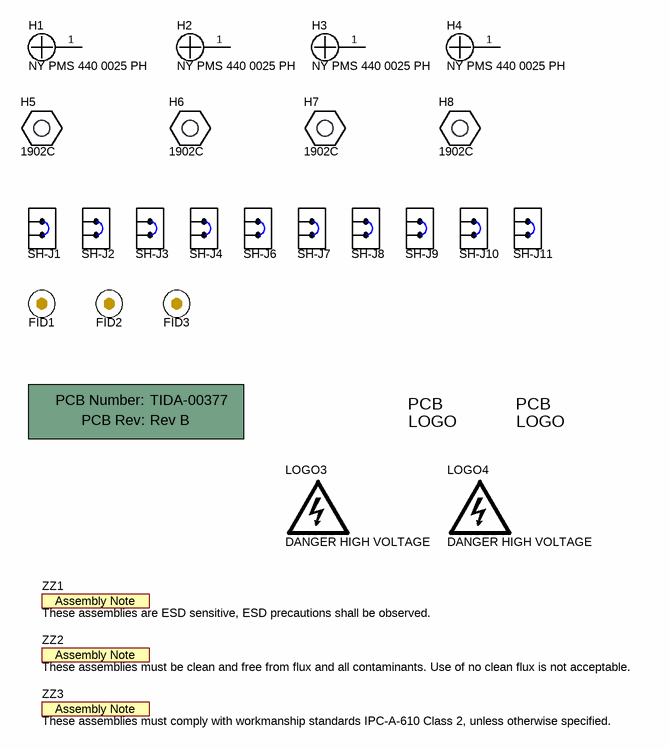
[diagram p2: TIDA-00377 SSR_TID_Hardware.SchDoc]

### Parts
!PCB1  Printed Circuit Board  (value not drawn)  (mechanical)
FCC_Disclaimer  FCC disclaimer  [FCC_disclaimer]  (value not drawn)  (no BOM)
FID1  Fiducial  [Fiducial10-20]  (value not drawn)
FID2  Fiducial  [Fiducial10-20]  (value not drawn)
FID3  Fiducial  [Fiducial10-20]  (value not drawn)
H1  NY PMS 440 0025 PH  [NY PMS 440 0025 PH]
H2  NY PMS 440 0025 PH  [NY PMS 440 0025 PH]
H3  NY PMS 440 0025 PH  [NY PMS 440 0025 PH]
H4  NY PMS 440 0025 PH  [NY PMS 440 0025 PH]
H5  1902C  [Keystone_1902C]
H6  1902C  [Keystone_1902C]
H7  1902C  [Keystone_1902C]
H8  1902C  [Keystone_1902C]
LOGO3  DANGER HIGH VOLTAGE  [IEC_HighVoltage_Small]  (no BOM)
LOGO4  DANGER HIGH VOLTAGE  [IEC_HighVoltage_Small]  (no BOM)
Logo?  EU RoHS Exempt Logo  [EURoHS_Exempt_60mil]  (value not drawn)  (no BOM)
SH-J1  SPC02SYAN  [SPC02SYAN]  (value not drawn)
SH-J2  SPC02SYAN  [SPC02SYAN]  (value not drawn)
SH-J3  SPC02SYAN  [SPC02SYAN]  (value not drawn)
SH-J4  SPC02SYAN  [SPC02SYAN]  (value not drawn)
SH-J6  SPC02SYAN  [SPC02SYAN]  (value not drawn)
SH-J7  SPC02SYAN  [SPC02SYAN]  (value not drawn)
SH-J8  SPC02SYAN  [SPC02SYAN]  (value not drawn)
SH-J9  SPC02SYAN  [SPC02SYAN]  (value not drawn)
SH-J10  SPC02SYAN  [SPC02SYAN]  (value not drawn)
SH-J11  SPC02SYAN  [SPC02SYAN]  (value not drawn)
ZZ1  These assemblies are ESD sensitive, ESD precautions shall be observed.  [AssemblyNote]  (no BOM)
ZZ2  These assemblies must be clean and free from flux and all contaminants. Use of no clean flux is not acceptable.  [AssemblyNote]  (no BOM)
ZZ3  These assemblies must comply with workmanship standards IPC-A-610 Class 2, unless otherwise specified.  [AssemblyNote]  (no BOM)

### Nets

Not connected (* = marked no-connect by the designer): H1 1; H2 1; H3 1; H4 1

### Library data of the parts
!PCB1 = PCB: Manufacturer: Any; PartNumber: TIDA-00377; SymbolCreator: a0412235
FCC_Disclaimer = FCC_disclaimer: SymbolCreator: a0412235
FID1-FID3 = Fiducial: Fiducial mark.  There is nothing to buy or mount.; SymbolCreator: codlsc
H1-H4 = NY PMS 440 0025 PH: Machine Screw, Round, #4-40 x 1/4, Nylon, Philips panhead; Manufacturer: B&F Fastener Supply; CompType: Hardware; SymbolCreator: codlsc; U/M: EA
H5-H8 = 1902C: Standoff, Hex, 0.5"L #4-40 Nylon; Manufacturer: Keystone; CompType: Hardware
LOGO3 LOGO4 = IEC_HighVoltage: IEC 61010-1 High Voltage Warning; SymbolCreator: a0412235
Logo? = EURoHS_Exempt: SymbolCreator: a0412235
SH-J1-SH-J4 SH-J6-SH-J11 = SPC02SYAN: Shunt, 100mil, Flash Gold, Black; Manufacturer: Sullins Connector Solutions; Value: 1x2; Note: You can "mate" this to a header by matching the designator.  i.e. use SH-J3 for header J3
ZZ1-ZZ3 = AssemblyNote: SymbolCreator: codlsc

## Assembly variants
001: not fitted FID1 FID2 FID3 H1 H2 H3 H4 H5 H6 H7 H8 R3 R17 R24 R27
